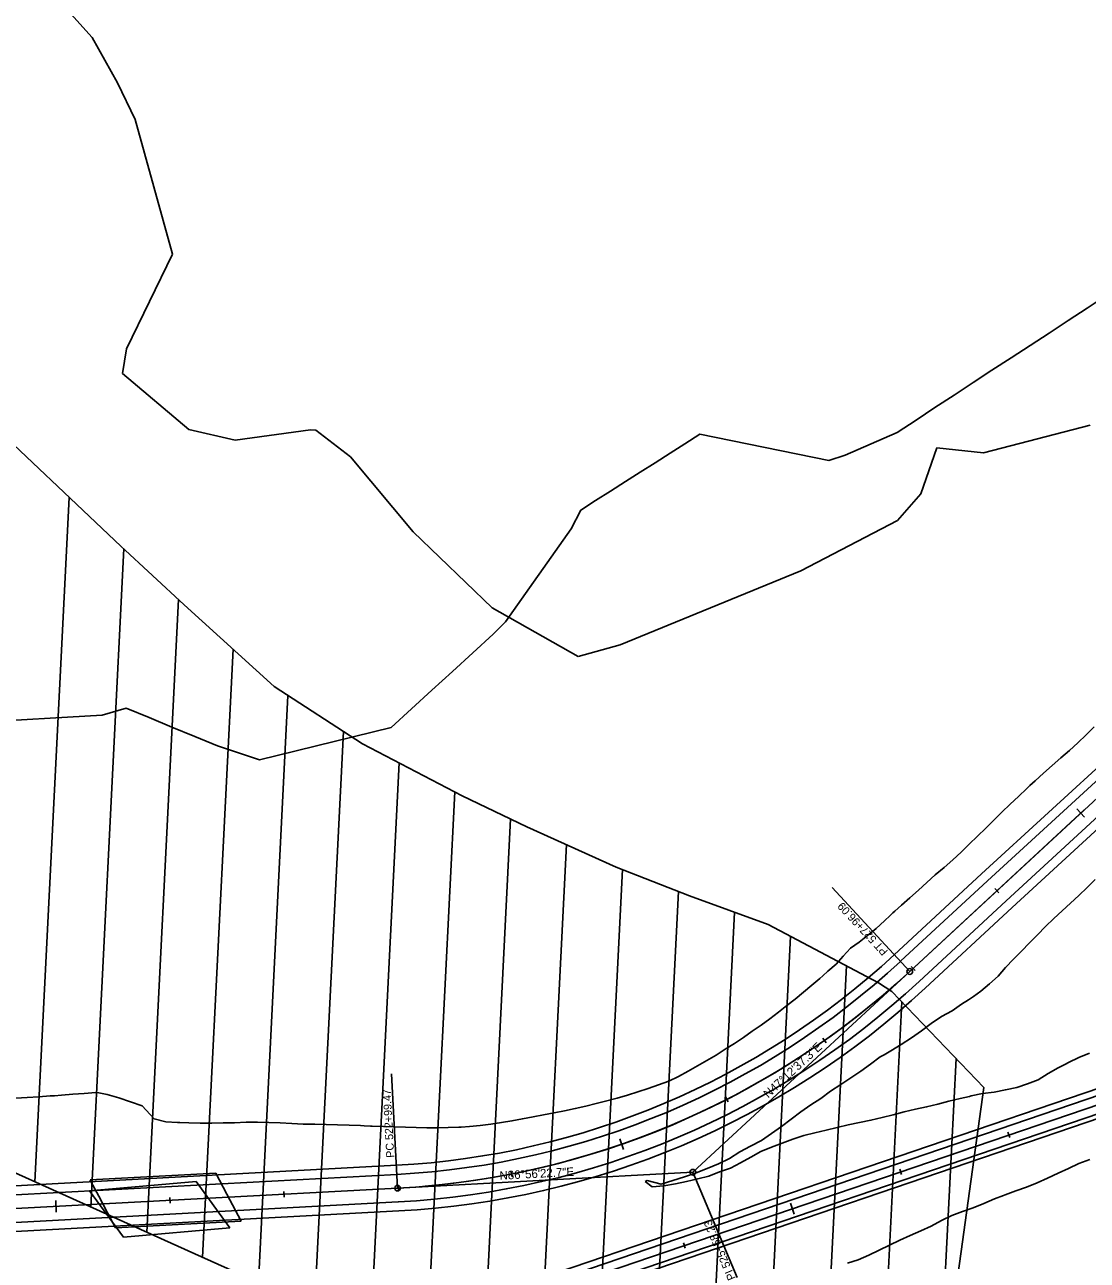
# Model space of a CAD drawing. Extents: x 1300404 to 1323571, y 234004 to 252077.
# Drawn here: x 1310592 to 1311522, y 241789 to 242870 of the extents above; entities that cross this region are included whole.
import ezdxf

# ---------------------------------------------------------------- set-up
doc = ezdxf.new("R2010")
doc.units = 0
for name, color, linetype in [('R_Bridge', 7, 'Continuous'), ('R_BRIDGE OLD', 7, 'Continuous'), ('R_Const Limits', 7, 'Continuous'), ('R_Floodway', 7, 'Continuous'), ('R_Flooplain', 7, 'Continuous'), ('R_Horz Alg Annot', 7, 'Continuous'), ('R_Horz Alg Annot Leader', 7, 'Continuous'), ('R_Horz Alg Major Ticks', 7, 'Continuous'), ('R_Horz Alg Minor Ticks', 7, 'Continuous'), ('R_Horz Alg Tangents', 7, 'Continuous'), ('R_Horz Alg Tangents Text', 7, 'Continuous'), ('R_Lane Edge', 7, 'Continuous'), ('R_Proposed', 7, 'Continuous'), ('R_Shoulder', 7, 'Continuous'), ('T_Drafting', 7, 'Continuous')]:
    doc.layers.add(name, color=color, linetype=linetype)

msp = doc.modelspace()

# ---------------------------------------------------------------- linework, layer by layer
at = {"layer": 'R_Bridge'}
for p, q in [((1310649.3, 241859.8), (1310759.3, 241865.7)), ((1310671.5, 241817.7), (1310781.5, 241823.6))]:
    msp.add_line(p, q, dxfattribs=at)
for points in [[(1310759.3, 241865.7), (1310769, 241847.4), (1310781.5, 241823.6)], [(1310649.3, 241859.8), (1310649.9, 241858.3), (1310656.8, 241845.4), (1310664.5, 241830.9), (1310671.5, 241817.7)]]:
    msp.add_lwpolyline(points, dxfattribs=at)
at = {"layer": 'R_BRIDGE OLD'}
for p, q in [((1310648.8, 241850.3), (1310741.9, 241858.4)), ((1310741.9, 241858.4), (1310771.6, 241817.7)), ((1310648.8, 241850.3), (1310678.5, 241809.6)), ((1310678.5, 241809.6), (1310771.6, 241817.7))]:
    msp.add_line(p, q, dxfattribs=at)
at = {"layer": 'R_Const Limits'}
for points in [[(1311538.5, 242633.4), (1311521.9, 242622.5), (1311505.3, 242611.6), (1311488.6, 242600.7), (1311472, 242589.9), (1311455.4, 242579), (1311438.7, 242568.1), (1311422.1, 242557.3), (1311405.5, 242546.4), (1311388.8, 242535.5), (1311372.2, 242524.6), (1311355.6, 242513.8), (1311310.2, 242493.8), (1311295.8, 242489.3), (1311183, 242512.1), (1311169.9, 242503.8), (1311156.9, 242495.5), (1311143.9, 242487.2), (1311130.8, 242478.9), (1311117.8, 242470.7), (1311104.8, 242462.4), (1311091.7, 242454.1), (1311078.7, 242445.8), (1311070.2, 242429.4), (1311012.7, 242347.9), (1311002, 242337.1), (1310984.1, 242320.8), (1310966.3, 242304.5), (1310948.4, 242288.2), (1310930.5, 242271.9), (1310912.7, 242255.6), (1310797.6, 242227.3), (1310785.3, 242231.4), (1310773, 242235.5), (1310760.7, 242239.6), (1310740.8, 242247.8), (1310720.8, 242256), (1310700.9, 242264.2), (1310680.9, 242272.4), (1310659.8, 242266.4), (1310548.2, 242259.9)], [(1310584.3, 241931.2), (1310594.2, 241931.8), (1310604.2, 241932.5), (1310614.2, 241933.2), (1310618, 241933.4), (1310624.2, 241933.9), (1310634.1, 241934.7), (1310644.1, 241935.4), (1310654.1, 241936.2), (1310655.4, 241936.2), (1310664.2, 241934.6), (1310674.4, 241931.5), (1310684.6, 241928.1), (1310694.8, 241924.6), (1310705.4, 241913.3), (1310715.5, 241910.5), (1310725.6, 241910.1), (1310727.6, 241910.1), (1310735.6, 241909.7), (1310745.6, 241909.5), (1310755.7, 241909.4), (1310765.7, 241909.7), (1310775.7, 241909.8), (1310785.7, 241910.2), (1310795.7, 241910.2), (1310805.7, 241910), (1310815.7, 241909.6), (1310825.8, 241909.2), (1310835.8, 241908.6), (1310845.8, 241908.5), (1310855.9, 241908.2), (1310865.9, 241907.8), (1310875.9, 241907.6), (1310886, 241907.2), (1310889.2, 241907.1), (1310894.6, 241906.9), (1310896, 241906.9), (1310906, 241906.6), (1310916, 241906.3), (1310925.3, 241905.9), (1310934.6, 241905.5), (1310944, 241905.3), (1310953.3, 241905.4), (1310962.7, 241905.5), (1310972, 241905.8), (1310973.9, 241905.9), (1310981.4, 241906.5), (1310990.7, 241907.4), (1311000, 241908.6), (1311009.3, 241909.9), (1311018.5, 241911.4), (1311027.7, 241913.2), (1311037, 241914.8), (1311046.1, 241916.7), (1311055.4, 241918.5), (1311064.6, 241920.3), (1311073.9, 241922.2), (1311083.1, 241924.3), (1311092.2, 241926.6), (1311101.4, 241928.9), (1311110.5, 241931.4), (1311119.6, 241934), (1311128.7, 241936.8), (1311137.8, 241939.7), (1311146.8, 241942.8), (1311155.7, 241946), (1311164.2, 241950.2), (1311172.6, 241954.8), (1311180.8, 241959.4), (1311189.1, 241964.2), (1311197.2, 241969), (1311205.2, 241974.1), (1311213.2, 241979.2), (1311221.1, 241984.4), (1311228.8, 241989.8), (1311236.5, 241995.2), (1311244.2, 242000.8), (1311251.7, 242006.5), (1311259.2, 242012.2), (1311266.5, 242018), (1311273.8, 242024), (1311281, 242030), (1311288.1, 242036.1), (1311290.6, 242038.4), (1311295.1, 242042.4), (1311302.2, 242048.4), (1311308.5, 242055.5), (1311314.7, 242062.6), (1311322.5, 242067.8), (1311329.8, 242073.6), (1311337.2, 242079.8), (1311344.7, 242086.4), (1311349.6, 242091.2), (1311351.9, 242093.3), (1311353.6, 242094.9), (1311359.4, 242100), (1311366.9, 242106.6), (1311374.3, 242113.3), (1311381.8, 242119.9), (1311389, 242126.8), (1311396.9, 242133), (1311404.4, 242139.7), (1311411.6, 242146.6), (1311418.8, 242153.6), (1311426, 242160.5), (1311433.2, 242167.5), (1311440.4, 242174.4), (1311447.4, 242181.5), (1311454.6, 242188.4), (1311461.9, 242195.3), (1311469.1, 242202.2), (1311471.7, 242204.7), (1311476.5, 242209), (1311483.9, 242215.7), (1311491.4, 242222.3), (1311498.9, 242228.9), (1311506.4, 242235.5), (1311513.9, 242242.2), (1311521.1, 242249.1), (1311528.1, 242256.2)], [(1311529.1, 242122.7), (1311522, 242115.7), (1311514.8, 242108.7), (1311507.4, 242102), (1311500.2, 242095.1), (1311492.7, 242088.5), (1311485.5, 242081.5), (1311478.5, 242074.3), (1311471.5, 242067.2), (1311464.6, 242059.9), (1311457.6, 242052.8), (1311450.6, 242045.5), (1311444.1, 242037.9), (1311436.5, 242031.4), (1311428.8, 242025), (1311422.6, 242020.3), (1311420.7, 242019), (1311418, 242017.4), (1311412.1, 242013.6), (1311403.8, 242007.8), (1311394.4, 242002.6), (1311385.4, 241996.7), (1311376.9, 241990.3), (1311368.2, 241984.1), (1311359.3, 241978.3), (1311350.2, 241972.6), (1311344.2, 241969.2), (1311340.8, 241967.4), (1311332.4, 241961), (1311323.8, 241955), (1311315.1, 241948.9), (1311306.3, 241943.2), (1311297.4, 241937.4), (1311288.9, 241931.1), (1311280.1, 241925.3), (1311271.4, 241919.2), (1311262.9, 241912.8), (1311254.3, 241906.5), (1311245.7, 241900.2), (1311236.9, 241894.1), (1311227.4, 241889.2), (1311218, 241884.2), (1311208.9, 241878.6), (1311199.4, 241873.8), (1311189.5, 241869.8), (1311179.6, 241865.8), (1311169.5, 241862.3), (1311159.3, 241859.1), (1311149.1, 241856), (1311136.7, 241859.2), (1311135, 241858.2)], [(1311135, 241858.2), (1311141.2, 241853.7), (1311151.5, 241854.6), (1311161.5, 241856.4), (1311171.3, 241858.4), (1311181.1, 241860.8), (1311190.9, 241863.1), (1311200.2, 241866.8), (1311209.7, 241869.9), (1311218.6, 241874.6), (1311227.5, 241879.5), (1311236.4, 241884.5), (1311245.6, 241888.3), (1311255.1, 241891.8), (1311264.3, 241895.5), (1311273.9, 241898.5), (1311283.6, 241900.8), (1311293.4, 241903.2), (1311303.2, 241905.5), (1311312.9, 241907.9), (1311322.8, 241909.9), (1311332.7, 241911.9), (1311342.5, 241914.2), (1311352.2, 241916.7), (1311361.9, 241919.3), (1311371.7, 241921.6), (1311381.5, 241923.6), (1311391.3, 241925.9), (1311401, 241928.6), (1311410.8, 241930.9), (1311419.1, 241932.8), (1311420.6, 241933.2), (1311430.4, 241935.3), (1311440.5, 241936.6), (1311450.4, 241938.6), (1311460.3, 241940.5), (1311469.8, 241943.7), (1311479.1, 241947.4), (1311487.8, 241952.8), (1311496.7, 241957.7), (1311503, 241961.1), (1311505.7, 241962.4), (1311514.8, 241966.8), (1311524, 241970.6)], [(1311524.2, 241877.5), (1311514.8, 241874), (1311505.7, 241869.7), (1311496.6, 241865.5), (1311487.4, 241861.3), (1311478.2, 241857.3), (1311469, 241853.3), (1311459.6, 241850.1), (1311450.2, 241846.6), (1311448.8, 241846), (1311440.8, 241843.1), (1311431.6, 241839.2), (1311422.3, 241835.4), (1311412.9, 241832.1), (1311403.5, 241828.6), (1311394.4, 241824.3), (1311385.5, 241819.4), (1311376.3, 241815.3), (1311367.2, 241811.2), (1311358.1, 241806.9), (1311348.9, 241802.7), (1311339.8, 241798.4), (1311330.8, 241793.9), (1311321.6, 241789.8), (1311312.1, 241786.8)]]:
    msp.add_lwpolyline(points, dxfattribs=at)
at = {"layer": 'R_Floodway'}
for p, q in [((1310600.8, 241858.1), (1310630.8, 242456.9)), ((1310649.8, 241836.1), (1310678.6, 242411.8)), ((1310698.8, 241814), (1310726.5, 242367.7)), ((1310747.7, 241792), (1310774.4, 242324)), ((1310796.7, 241770), (1310822.4, 242283.5)), ((1310845.6, 241748), (1310870.9, 242252.2)), ((1310894.6, 241726), (1310919.6, 242224.7)), ((1310943.6, 241704), (1310968.4, 242199.3)), ((1310992.5, 241682), (1311017.2, 242175.7)), ((1311041.5, 241660), (1311066.2, 242153.1)), ((1311090.3, 241635.8), (1311115.1, 242131.3)), ((1311139.1, 241610.3), (1311164.3, 242112.1)), ((1311187.9, 241584.9), (1311213.4, 242093.9)), ((1311236.7, 241559.4), (1311262.4, 242072.8)), ((1311285.5, 241534), (1311311.2, 242047.1)), ((1311334.3, 241508.5), (1311359.7, 242015.5)), ((1311383, 241481.9), (1311407.2, 241965.9))]:
    msp.add_line(p, q, dxfattribs=at)
for points in [[(1312719.3, 241174), (1312375.3, 241167.2), (1311696.9, 241341.7), (1311497.5, 241419.5), (1311333.8, 241508.8), (1311059.1, 241652.1), (1310740.8, 241795.1), (1310453.3, 241924.5), (1310367.2, 241994.2), (1310267.8, 242111.7), (1309996.2, 242391.6), (1309869.7, 242546.7), (1309624.5, 242919.6)], [(1310244.9, 242890.8), (1310303.3, 242800.7), (1310379.6, 242680.8), (1310490.2, 242568.7), (1310549, 242534.3), (1310676, 242414.2), (1310731.6, 242363), (1310810.3, 242291.3), (1310887.6, 242241.4), (1310974.9, 242195.9), (1311031.6, 242168.8), (1311109.7, 242133.4), (1311173.8, 242108.4), (1311242.7, 242083.2), (1311339.3, 242032.3), (1311351, 242024.5), (1311431.5, 241940.6), (1311405.2, 241750.8)]]:
    msp.add_lwpolyline(points, dxfattribs=at)
at = {"layer": 'R_Flooplain'}
for p, q in [((1310651, 242859.4), (1310614.4, 242900)), ((1310673.3, 242819.6), (1310651, 242859.4)), ((1310688.6, 242787.4), (1310673.3, 242819.6)), ((1310705, 242728.5), (1310688.6, 242787.4)), ((1310721.4, 242669.6), (1310705, 242728.5)), ((1310681, 242586.9), (1310721.4, 242669.6)), ((1310677.5, 242565.3), (1310681, 242586.9)), ((1310735.6, 242516.4), (1310677.5, 242565.3)), ((1310776.2, 242507.1), (1310735.6, 242516.4)), ((1310842, 242515.9), (1310776.2, 242507.1)), ((1310846.8, 242515.7), (1310842, 242515.9)), ((1310877.1, 242492.4), (1310846.8, 242515.7)), ((1311524.5, 242520.2), (1311431.4, 242495.9)), ((1310931.9, 242426.7), (1310877.1, 242492.4)), ((1311390.5, 242500.4), (1311376.4, 242460)), ((1311431.4, 242495.9), (1311390.5, 242500.4)), ((1311376.4, 242460), (1311355.9, 242436.8)), ((1311001.2, 242360.3), (1310931.9, 242426.7)), ((1311355.9, 242436.8), (1311271.4, 242392.7)), ((1311271.4, 242392.7), (1311113.3, 242328)), ((1311076.5, 242317.8), (1311001.2, 242360.3)), ((1311113.3, 242328), (1311076.5, 242317.8))]:
    msp.add_line(p, q, dxfattribs=at)
at = {"layer": 'R_Horz Alg Annot Leader'}
for points in [[(1311366.7, 242042.1), (1311298.8, 242115.5)], [(1310918.4, 241852.6), (1310913.1, 241952.4)], [(1311176.8, 241866.4), (1311215.7, 241774.3)]]:
    msp.add_lwpolyline(points, dxfattribs=at)
at = {"layer": 'R_Horz Alg Major Ticks'}
for points in [[(1311512.9, 242184.3), (1311519.7, 242177)], [(1311112.9, 241895.7), (1311116.2, 241886.2)], [(1310619.1, 241841.6), (1310619.6, 241831.6)], [(1311262.4, 241839.3), (1311265.6, 241829.9)]]:
    msp.add_lwpolyline(points, dxfattribs=at)
at = {"layer": 'R_Horz Alg Minor Ticks'}
for points in [[(1311441.2, 242114.6), (1311444.6, 242110.9)], [(1311367.9, 242046.6), (1311371.3, 242043)], [(1311290.6, 241983.8), (1311293.4, 241979.7)], [(1311205.3, 241932.4), (1311207.6, 241928)], [(1311452.5, 241901.4), (1311454.2, 241896.7)], [(1311017.6, 241867.4), (1311018.6, 241862.5)], [(1311357.9, 241869.2), (1311359.5, 241864.5)], [(1310918.8, 241855.1), (1310919.1, 241850.1)], [(1310719.1, 241844.4), (1310719.3, 241839.4)], [(1310818.9, 241849.7), (1310819.2, 241844.7)], [(1311168.5, 241804.7), (1311170.2, 241800)]]:
    msp.add_lwpolyline(points, dxfattribs=at)
at = {"layer": 'R_Horz Alg Tangents'}
for p, q in [((1311176.8, 241866.4), (1311366.7, 242042.1)), ((1310918.4, 241852.6), (1311176.8, 241866.4))]:
    msp.add_line(p, q, dxfattribs=at)
at = {"layer": 'R_Lane Edge'}
for p, q in [((1311434.8, 242121.5), (1311582.2, 242256.7)), ((1311451.1, 242103.9), (1311598.1, 242239.6)), ((1311434.8, 242121.5), (1311358.5, 242051)), ((1311451.1, 242103.9), (1311374.8, 242033.3)), ((1310713.2, 241655), (1311678.5, 241983.6)), ((1310718, 241640.8), (1311683.3, 241969.4)), ((1310472.7, 241840.7), (1310917.8, 241864.5)), ((1310533.3, 241819.9), (1310919, 241840.6))]:
    msp.add_line(p, q, dxfattribs=at)
for radius in [704.2, 728.2]:
    msp.add_arc((1310880.2, 242567.7), radius, 273.0604, 312.7896, dxfattribs=at)
at = {"layer": 'R_Proposed'}
for p, q in [((1311366.7, 242042.1), (1311589.7, 242248.6)), ((1311519.4, 242183.5), (1311366.7, 242042.1)), ((1311366.7, 242042.1), (1311519.4, 242183.5)), ((1311366.7, 242042.1), (1311519.4, 242183.5)), ((1310715.6, 241647.9), (1311680.9, 241976.5)), ((1310473.4, 241828.8), (1310918.4, 241852.6))]:
    msp.add_line(p, q, dxfattribs=at)
for centre in [(1311366.7, 242042.1), (1311176.8, 241866.4), (1310918.4, 241852.6)]:
    msp.add_circle(centre, 2.5, dxfattribs=at)
for start in [273.0604, 273.0604, 274.9846, 274.9846]:
    msp.add_arc((1310880.2, 242567.7), 716.2, start, 312.7896, dxfattribs=at)
at = {"layer": 'R_Shoulder'}
for p, q in [((1311429.4, 242127.4), (1311576.8, 242262.6)), ((1311456.5, 242098.1), (1311603.5, 242233.7)), ((1311429.4, 242127.4), (1311353.1, 242056.8)), ((1311456.5, 242098.1), (1311380.3, 242027.5)), ((1310711.2, 241660.7), (1311676.5, 241989.3)), ((1310766.6, 241653.1), (1311684.6, 241965.6)), ((1310472.3, 241848.7), (1310917.3, 241872.5)), ((1310533.7, 241812), (1310919.5, 241832.6))]:
    msp.add_line(p, q, dxfattribs=at)
for radius in [696.2, 736.2]:
    msp.add_arc((1310880.2, 242567.7), radius, 273.0604, 312.7896, dxfattribs=at)
at = {"layer": 'T_Drafting'}
msp.add_line((1310473.4, 241828.8), (1310918.4, 241852.6), dxfattribs=at)

# ---------------------------------------------------------------- texts
at = {"layer": 'R_Horz Alg Annot'}
for s, rotation, p in [('PT 527+96.09', 132.7896, (1311348.1, 242060)), ('PC 522+99.47', 93.0604, (1310915.5, 241879.3)), ('PI 525+58.23', 112.925, (1311214.4, 241773.7))]:
    msp.add_text(s, height=7, rotation=rotation, dxfattribs=at).set_placement(p)
at = {"layer": 'R_Horz Alg Tangents Text'}
for s, rotation, p in [('N47%%d12\'37.3"E', 42.7896, (1311242.8, 241930.9)), ('N86%%d56\'22.7"E', 3.0604, (1311007.8, 241859.8))]:
    msp.add_text(s, height=7.5, rotation=rotation, dxfattribs=at).set_placement(p)

doc.saveas('drawing.dxf')
